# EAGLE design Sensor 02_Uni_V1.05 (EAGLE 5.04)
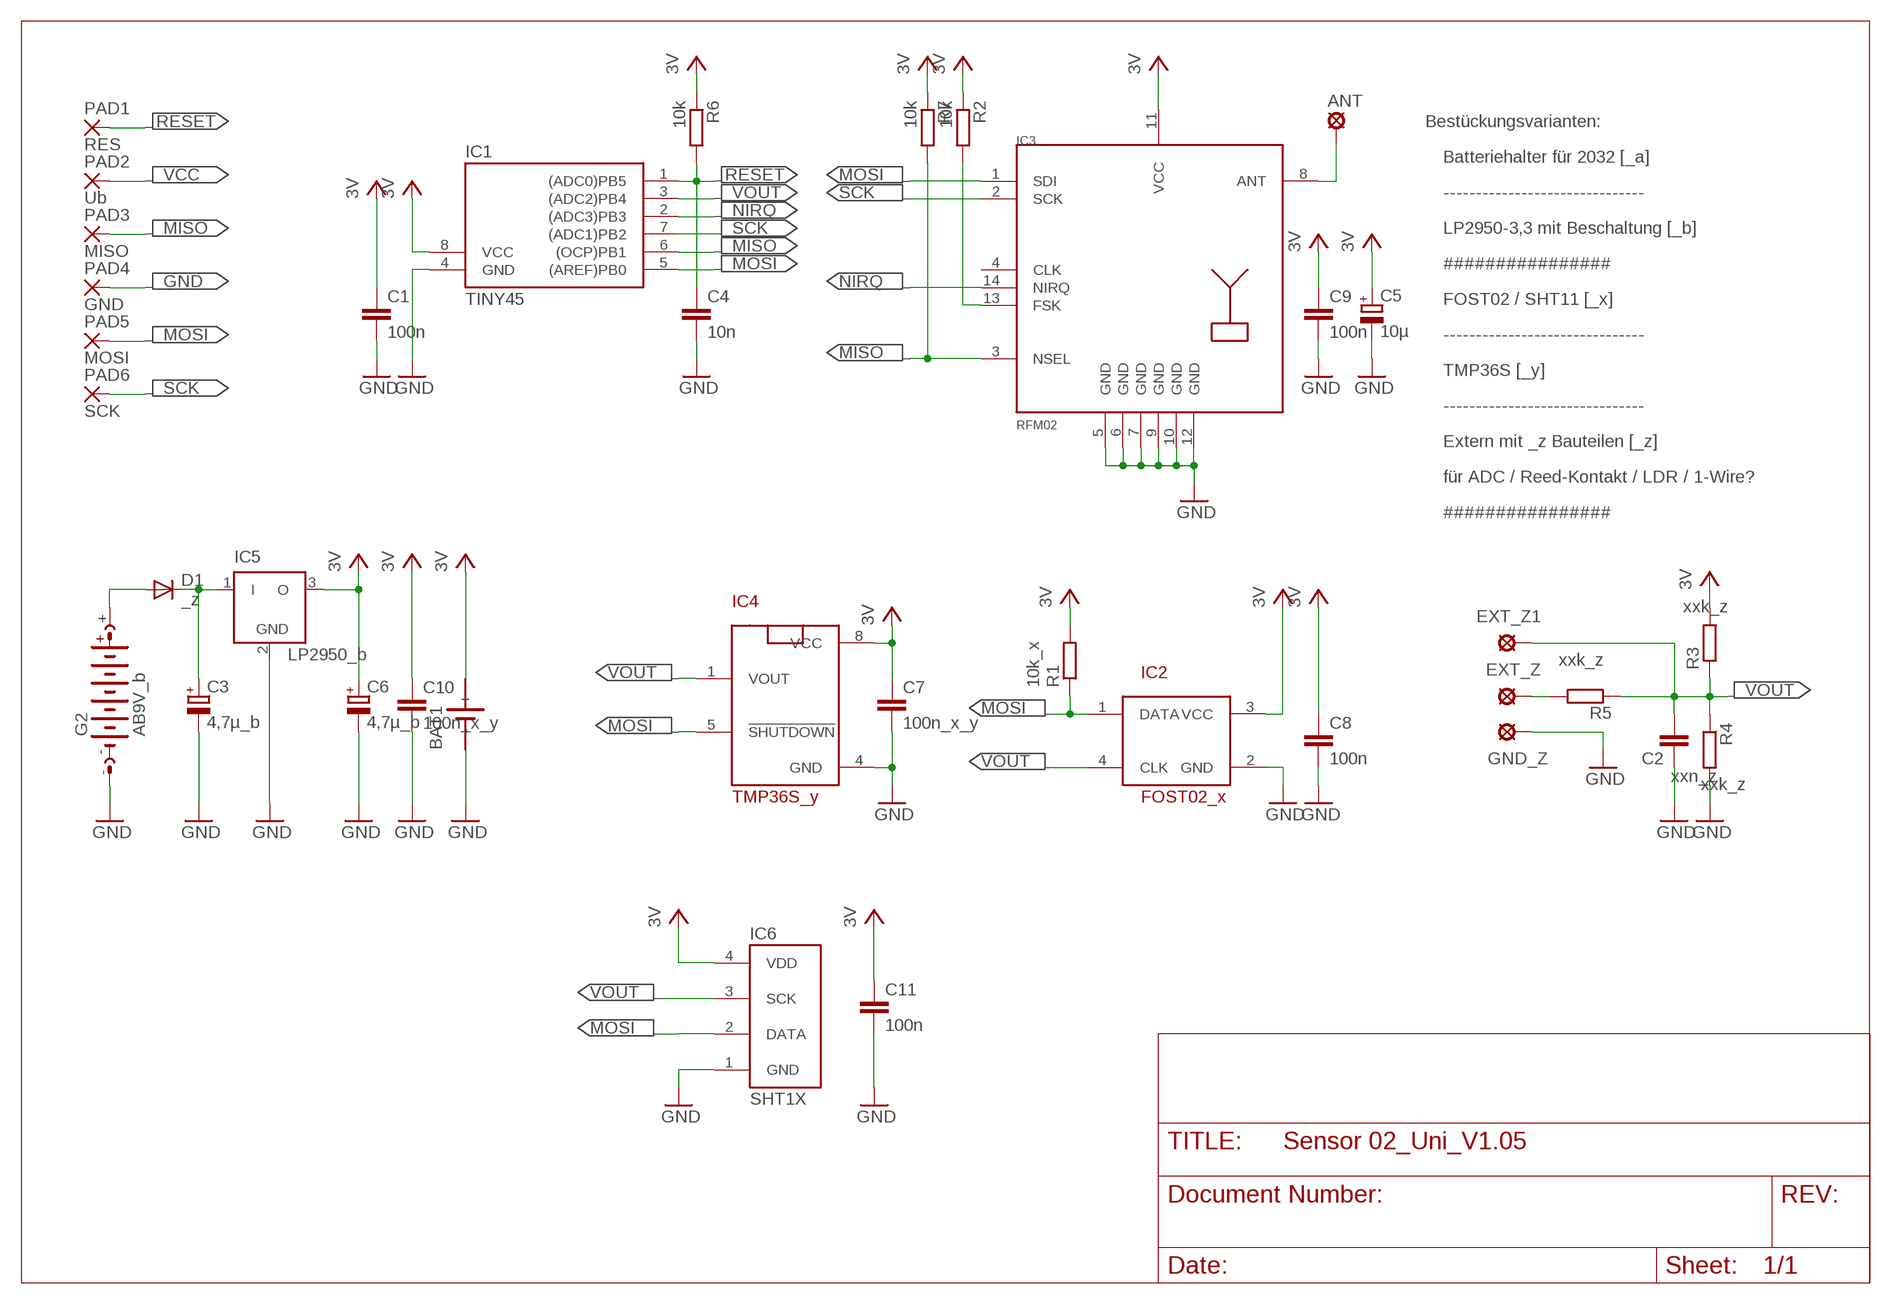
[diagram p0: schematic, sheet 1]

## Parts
ANT  ANT  LSP10  [LSP10]
BAT1  SN2032  [SN2032]
C1  100n  C-EUC0805  [C0805]
C2  xxn_z  C-EUC0805  [C0805]
C3  4,7µ_b  CPOL-EUCT6032  [CT6032]
C4  10n  C-EUC0805  [C0805]
C5  10µ  CPOL-EUCT6032  [CT6032]
C6  4,7µ_b  CPOL-EUCT6032  [CT6032]
C7  100n_x_y  C-EUC0805  [C0805]
C8  100n  C-EUC0805  [C0805]
C9  100n  C-EUC0805  [C0805]
C10  100n_x_y  C-EUC0805  [C0805]
C11  100n  C-EUC0805  [C0805]
D1  _z  DIODE-MINIMELF  [MINIMELF]
EXT_Z  LSP10  [LSP10]
EXT_Z1  LSP10  [LSP10]
G2  AB9V_b  AB9V  [AB9V]
GND_Z  LSP10  [LSP10]
IC1  TINY45  TINY25-20SU  [SOIC8]
IC2  FOST02_x  FOST02  [FOST02]
IC3  RFM02  [RFM]
IC4  TMP36S_y  TMP36S  [SO8]
IC5  LP2950_b  LP2950  [DPACK]
IC6  SHT1X  [SHT1X]
PAD1  RES  SMD2  [SMD1,27-2,54]
PAD2  Ub  SMD2  [SMD1,27-2,54]
PAD3  MISO  SMD2  [SMD1,27-2,54]
PAD4  GND  SMD2  [SMD1,27-2,54]
PAD5  MOSI  SMD2  [SMD1,27-2,54]
PAD6  SCK  SMD2  [SMD1,27-2,54]
R1  10k_x  R-EU_R0805  [R0805]
R2  10k  R-EU_R0805  [R0805]
R3  xxk_z  R-EU_R0805  [R0805]
R4  xxk_z  R-EU_R0805  [R0805]
R5  xxk_z  R-EU_R0805  [R0805]
R6  10k  R-EU_R0805  [R0805]
R7  10k  R-EU_R0805  [R0805]

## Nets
GND: BAT1.- C1.2 C2.1 C3.- C4.2 C5.- C6.- C7.2 C8.2 C9.2 C10.2 C11.2 G2.- GND_Z.MP IC1.4(GND) IC2.2(GND) IC3.5(GND) IC3.6(GND) IC3.7(GND) IC3.9(GND) IC3.10(GND) IC3.12(GND) IC4.4(GND) IC5.2(GND) IC6.1(GND) PAD4.1(P) R4.2
MISO: IC1.6((OCP)PB1) IC3.3(NSEL) PAD3.1(P) R7.2
MOSI: IC1.5((AREF)PB0) IC2.1(DATA) IC3.1(SDI) IC4.5(!SHUTDOWN!) IC6.2(DATA) PAD5.1(P) R1.1
N$1: EXT_Z.MP R5.2
N$2: C3.+ D1.C IC5.1(I)
N$7: ANT.MP IC3.8(ANT)
N$8: IC3.13(FSK) R2.2
N$14: D1.A G2.+
NIRQ: IC1.2((ADC3)PB3) IC3.14(NIRQ)
RESET: C4.1 IC1.1((ADC0)PB5) PAD1.1(P) R6.2
SCK: IC1.7((ADC1)PB2) IC3.2(SCK) PAD6.1(P)
VCC: BAT1.+ C1.1 C5.+ C6.+ C7.1 C8.1 C9.1 C10.1 C11.1 IC1.8(VCC) IC2.3(VCC) IC3.11(VCC) IC4.8(VCC) IC5.3(O) IC6.4(VDD) PAD2.1(P) R1.2 R2.1 R3.2 R6.1 R7.1 ; supply symbol labelled 3V
VOUT: C2.2 EXT_Z1.MP IC1.3((ADC2)PB4) IC2.4(CLK) IC4.1(VOUT) IC6.3(SCK) R3.1 R4.1 R5.1
Unconnected: IC3.4(CLK)

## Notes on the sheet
- Bestückungsvarianten:
- Batteriehalter für 2032 [_a]
- -------------------------------
- LP2950-3,3 mit Beschaltung [_b]
- ################
- FOST02 / SHT11 [_x]
- -------------------------------
- TMP36S [_y]
- -------------------------------
- Extern mit _z Bauteilen [_z]
- für ADC / Reed-Kontakt / LDR / 1-Wire?
- ################

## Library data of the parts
ANT EXT_Z EXT_Z1 GND_Z = solpad:LSP10: SOLDER PAD
BAT1 = sn2032:SN2032: LI BATTERY
C1 C2 C4 C7-C11 = rcl:C-EU: CAPACITOR, European symbol
C3 C5 C6 = rcl:CPOL-EU: POLARIZED CAPACITOR, European symbol
D1 = diode:DIODE-: DIODE
G2 = battery:AB9V: 9-V BATTERY CLIP
IC1 = avr-2:TINY25
IC2 = RFMxx:FOST02
IC3 = RFMxx:RFM02
IC4 = analog-devices:TMP36S
IC5 = linear:LP2950: 100 mA, Low Power Low Dropout Voltage Regulator Source: http://www.onsemi.com/pub/Collateral/LP2950-D.PDF
IC6 = sht10_11_15:SHT1X
PAD1-PAD6 = wirepad:SMD2: SMD PAD
R1-R7 = rcl:R-EU_: RESISTOR, European symbol

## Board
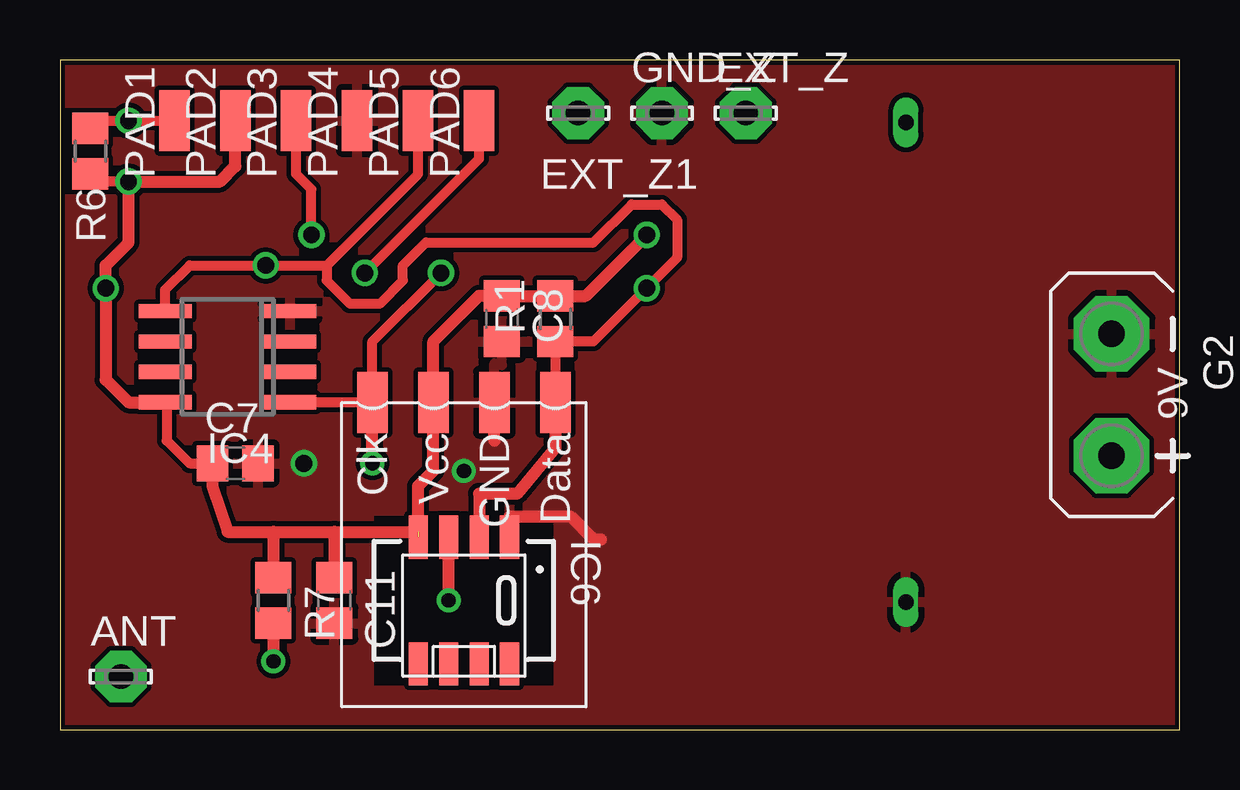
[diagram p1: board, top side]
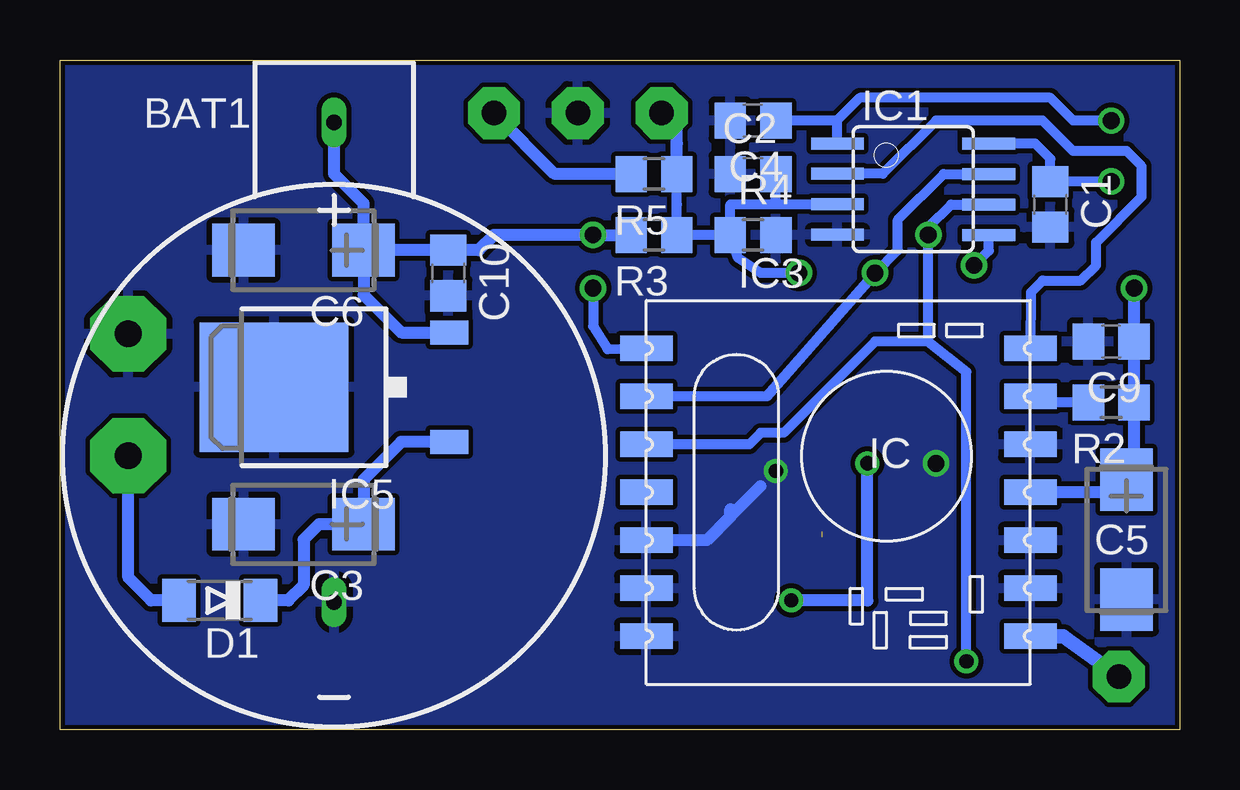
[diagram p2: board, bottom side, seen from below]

Size 46.66 x 27.93 mm. Coordinates in mm from the lower left corner, seen from the top.
Outline: 0,0 46.66,0 46.66,27.93 0,27.93 0,0
Copper layers (1*16): Top 0.035mm / dielectric 1.5mm / Bottom 0.035mm
Design rules "ZWILLING": minimum track width 0.2mm, minimum drill 0.5mm, track to track 0.2mm, track to pad 0.2mm, pad to pad 0.2mm, via to via 0.2mm, smd to smd 0mil, copper to edge 0.2mm, drill to drill 0.2mm, minimum pad ring 0.2mm, minimum via ring 0.2mm, stop-mask expansion 0.1mm, vias tented up to drill 0mil, thermal gap 10mil

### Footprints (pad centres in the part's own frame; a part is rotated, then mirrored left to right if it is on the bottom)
LSP10 = drill 1.016 pad 2.159 octagon: MP 0,0
SN2032 = drill 0.65 long: + 0,13.9; - 0,-6.1
C0805 = smd 1.3 x 1.5: 1 -0.95,0; 2 0.95,0
CT6032 = smd 2.6 x 2.2: + -2.5,0; - 2.5,0
MINIMELF = smd 1.4 x 1.8: A 1.7,0; C -1.7,0
AB9V = drill 1.118 pad 3.15 octagon: + 0,2.54; - 0,-2.54
SOIC8 = smd 0.5 x 2.2: 1 -1.27,-3.154; 2 -0.01,-3.154; 3 1.26,-3.154; 4 2.53,-3.154; 5 2.54,3.154; 6 1.27,3.154; 7 0,3.154; 8 -1.27,3.154
FOST02 = smd 1.27 x 2.54: 1 -3.81,-10.16; 2 -1.27,-10.16; 3 1.27,-10.16; 4 3.81,-10.16
RFM = smd 2.184 x 1.067: 1 0,14; 2 0,12; 3 0,10; 4 0,8; 5 0,6; 6 0,4; 7 0,2; 8 16,2; 9 16,4; 10 16,6; 11 16,8; 12 16,10; 13 16,12; 14 16,14
SO8 = smd 0.6 x 2.2: 1 -1.905,-2.6; 2 -0.635,-2.6; 3 0.635,-2.6; 4 1.905,-2.6; 5 1.905,2.6; 6 0.635,2.6; 7 -0.635,2.6; 8 -1.905,2.6
DPACK = smd 1 x 1.6: 1 -2.28,-4.8; 3 2.28,-4.8 | smd 5.4 x 6.2: 2 0,2.5
SHT1X = smd 1.803 x 0.8: 1 -2.642,1.905; 2 -2.642,0.635; 3 -2.642,-0.635; 4 -2.642,-1.905; 5 2.642,-1.905; 6 2.642,-0.635; 7 2.642,0.635; 8 2.642,1.905
SMD1,27-2,54 = smd 1.27 x 2.54: 1 0,0
R0805 = smd 1.3 x 1.5: 1 -0.95,0; 2 0.95,0

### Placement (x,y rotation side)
ANT  2.54,2.22 0 top
BAT1  35.24,11.43 0 bottom
C1  5.4,21.91 270 bottom
C2  17.78,23.18 0 bottom
C3  36.51,8.57 180 bottom
C4  17.78,25.4 180 bottom
C5  2.22,7.94 270 bottom
C6  36.51,20 180 bottom
C7  7.3,11.11 0 top
C8  18.41,17.14 270 top
C9  2.86,16.19 180 bottom
C10  30.48,19.05 270 bottom
C11  11.43,5.4 270 top
D1  40.01,5.4 180 bottom
EXT_Z  28.57,25.72 0 top
EXT_Z1  21.59,25.72 0 top
G2  43.81,13.97 180 top
GND_Z  25.08,25.72 0 top
IC1  11.11,23.18 270 bottom
IC2  16.83,3.49 180 top
IC3  22.23,1.91 0 bottom
IC4  6.99,15.56 90 top
IC5  35.24,14.29 90 bottom
IC6  16.83,5.4 270 top
PAD1  4.76,25.4 0 top
PAD2  7.3,25.4 0 top
PAD3  9.84,25.4 0 top
PAD4  12.38,25.4 0 top
PAD5  14.92,25.4 0 top
PAD6  17.46,25.4 0 top
R1  20.64,17.14 90 top
R2  2.86,13.65 180 bottom
R3  21.91,20.64 180 bottom
R4  17.78,20.64 0 bottom
R5  21.91,23.18 180 bottom
R6  1.27,24.13 90 top
R7  8.89,5.4 270 top

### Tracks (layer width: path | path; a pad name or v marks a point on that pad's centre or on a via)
GND  (via drill 0.6, 0.7)
  Top 0.508: 18.1,12.06 IC2.2 | IC6.1 18.73,8.89 21.27,8.89 22.23,7.94 22.54,7.94
  Bottom 0.508: IC3.5 19.72,7.91 18.73,8.89 | 18.73,8.89 18.73,9.21 | 17.46,10.16 18.73,8.89
  other vias: 10.16,11.11 16.83,10.79
  pour Bottom: 0,0 0,27.94 46.67,27.94 46.67,0
  pour Top: 0,0 0,27.94 46.67,27.94 46.67,0
MISO  (via drill 0.6, 0.7)
  Top 0.406: v10.48,20.64 10.48,22.54 9.84,23.18 PAD3.1
  Top 0.508: R7.2 v8.89,2.86
  Bottom 0.406: IC1.6 9.53,21.91 10.48,20.95 v10.48,20.64 10.48,16.19 | IC3.3 17.94,11.9 17.46,12.38 16.51,12.38 12.7,16.19 10.48,16.19 | v8.89,2.86 8.89,14.92 10.48,16.18 10.48,16.19
MOSI  (via drill 0.7)
  Top 0.406: PAD5.1 14.92,23.18 11.11,19.37 | 11.11,18.73 12.06,17.78 13.34,17.78 14.29,18.73 14.29,19.37 15.24,20.32 22.23,20.32 23.81,21.91 25.08,21.91 25.72,21.27 25.72,19.68 v24.45,18.41 22.23,16.2 R1.1 IC2.1 | 11.11,18.73 11.43,18.41 | 11.11,19.37 v8.57,19.37 5.4,19.37 4.38,18.36 IC4.5 | 11.11,19.37 11.11,18.73
  Top 0.508: IC6.2 17.46,9.84 19.05,9.84 20.64,11.75 IC2.1
  Bottom 0.406: IC1.5 7.96,19.98 v8.57,19.37 | IC3.1 23.84,15.88 24.45,16.83 v24.45,18.41
N$1
  Bottom 0.406: EXT_Z.MP 27.94,25.4
  Bottom 0.508: R5.2 26.04,23.18 EXT_Z.MP
N$2
  Bottom 0.508: IC5.1 32.44,12.01 34.01,10.44 C3.+ 35.88,8.57 36.51,7.94 36.51,6.03 37.15,5.4 D1.C
N$7
  Bottom 0.61: IC3.8 4.86,3.9 ANT.MP
N$8
  Bottom 0.406: 5.78,13.9 IC3.13 6.16,13.65 R2.2
N$14
  Bottom 0.508: G2.+ 43.81,6.35 42.86,5.4 D1.A
NIRQ
  Bottom 0.406: IC1.2 12.37,23.19 10.16,25.4 5.71,25.4 4.45,24.13 2.22,24.13 1.59,23.5 1.59,22.23 3.49,20.32 3.49,19.37 4.13,18.73 5.71,18.73 6.2,18.25 6.2,17.46 IC3.14
RESET  (via drill 0.7)
  Top 0.406: PAD1.1 v2.86,25.4 1.27,25.4 R6.2
  Bottom 0.406: 14.29,25.4 C4.1 | v2.86,25.4 4.45,25.4 5.4,26.35 13.34,26.35 14.29,25.4 | 14.29,25.4 14.29,24.47 IC1.1
SCK  (via drill 0.7)
  Top 0.406: PAD6.1 17.46,23.81 v12.7,19.05
  Bottom 0.406: IC1.7 9.84,23.18 11.75,21.27 11.75,20 v12.7,19.05 17.21,13.9 IC3.2
VCC  (via drill 0.7)  (1 unrouted)
  Top 0.406: R6.1 1.27,22.86 v2.86,22.86 | IC4.8 4.45,13.59 4.45,12.06 5.4,11.11 C7.1
  Top 0.508: PAD2.1 7.3,23.5 6.67,22.86 v2.86,22.86 2.86,20.32 1.91,19.37 v1.91,18.41 1.91,14.61 2.86,13.65 IC4.8 | v24.45,20.64 21.91,18.09 R1.2 C8.1 17.46,18.1 15.56,16.19 IC2.3 15.56,10.79 14.92,10.16 14.92,8.26 11.43,8.26 | C7.1 6.35,10.16 6.99,8.26 8.89,8.26 | 8.89,8.26 11.43,8.26 | 11.43,8.26 C11.1 | 8.89,8.26 R7.1
  Bottom 0.406: IC1.8 6.03,24.45 5.4,23.81 C1.1 v2.86,22.86 | 2.01,9.9 C5.+
  Bottom 0.508: R3.2 v24.45,20.64 28.57,20.64 29.21,20 C10.1 C6.+ | v1.91,18.41 1.91,16.83 1.91,14.61 | IC5.3 32.44,16.57 34.01,18.14 C6.+ | BAT1.+ 35.24,23.18 34.01,21.95 C6.+ | 1.91,14.61 C9.1 | C5.+ 2.18,10.48 1.91,10.48 R2.1 1.91,14.61 | 2.01,9.9 IC3.11
VOUT  (via drill 0.6, 0.7)
  Top 0.406: v15.88,19.05 13.02,16.19 IC2.4 IC4.1
  Top 0.508: v13.02,11.11 IC2.4 | v16.19,5.4 IC6.3
  Bottom 0.406: 16.83,21.92 18.72,21.92 18.73,21.91 R4.1 | 16.83,21.92 IC1.3 | R5.1 20.96,21.91 20.95,21.91 20.96,21.91 R3.1 R4.1 | R4.1 18.41,19.68 17.46,19.05 v15.88,19.05 | C2.2 16.83,21.92
  Bottom 0.508: R5.1 20.96,24.45 20.95,24.45 20.95,25.08 EXT_Z1.MP | v13.02,11.11 13.02,5.4 v16.19,5.4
